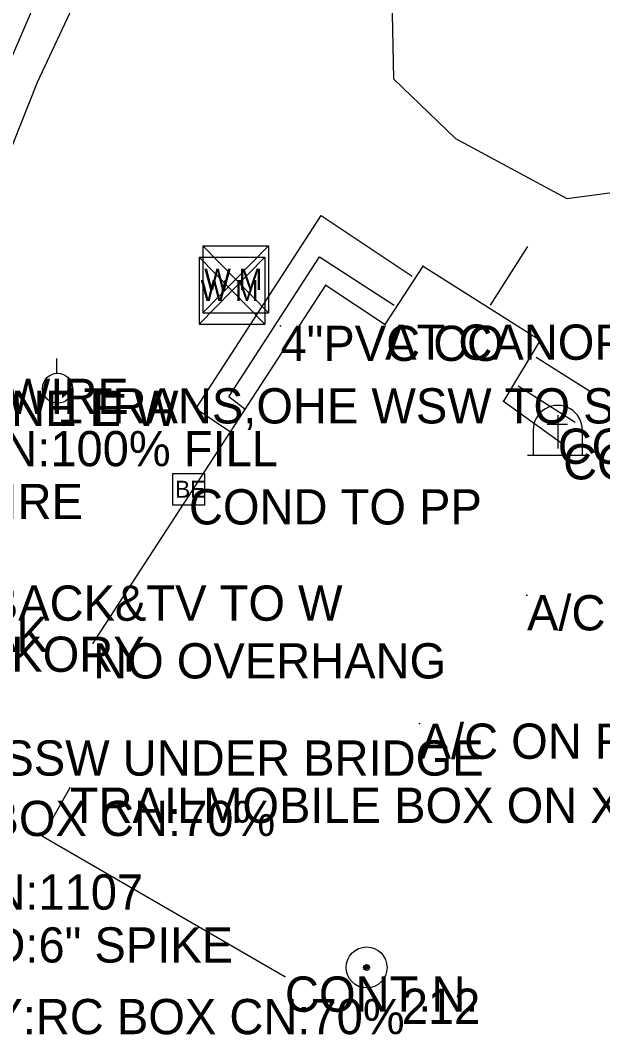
# Model space of a CAD drawing. Extents: x 997398 to 1003416, y 334596 to 337085.
# Drawn here: x 999521.1 to 999603.8, y 336058.6 to 336202.6 of the extents above; entities that cross this region are included whole.
import ezdxf

# ---------------------------------------------------------------- set-up
doc = ezdxf.new("R2010")
doc.units = 0
for name, color, linetype in [('S_BUILDING', 7, 'Continuous'), ('S_BUILDING_ANNOT', 7, 'Continuous'), ('S_CROSS_DRAIN_ANNOT', 7, 'Continuous'), ('S_DITCHLINE', 7, 'Continuous'), ('S_EDGE_PAVEMENT', 7, 'Continuous'), ('S_ELECTRIC_UTILITIES', 7, 'Continuous'), ('S_ELECTRIC_UTILITIES_ANNOT', 7, 'Continuous'), ('S_GRAVEL_ROAD', 7, 'Continuous'), ('S_GRD_PT_SYM', 7, 'Continuous'), ('S_IRON_PIN', 7, 'Continuous'), ('S_IRON_PIN_ANNOT', 7, 'Continuous'), ('S_MISC_STRUCTURES_ANNOT', 7, 'Continuous'), ('S_MISC_TOPO_POINT', 7, 'Continuous'), ('S_MSC_PT_SYM', 7, 'Continuous'), ('S_SECONDARY_CTL_ANNOT', 7, 'Continuous'), ('S_SIDE_DRAIN_ANNOT', 7, 'Continuous'), ('S_SIDEWALK', 7, 'Continuous'), ('S_STR_PT_SYM', 7, 'Continuous'), ('S_TOMBSTONE', 7, 'Continuous'), ('S_TOMBSTONE_ANNOT', 7, 'Continuous'), ('S_TREE_ANNOT', 7, 'Continuous'), ('S_UTILITY_POLE', 7, 'Continuous'), ('S_UTILITY_POLE_ANNOT', 7, 'Continuous'), ('S_WATER_UTILITIES', 7, 'Continuous')]:
    doc.layers.add(name, color=color, linetype=linetype)

msp = doc.modelspace()

# ---------------------------------------------------------------- linework, layer by layer
at = {"layer": 'S_BUILDING'}
for p, q in [((999572.9, 336159.41), (999578.28, 336167.71)), ((999578.28, 336167.71), (999594.93, 336157.21)), ((999531.42, 336114.19), (999564.46, 336164.99)), ((999564.46, 336164.99), (999572.9, 336159.41)), ((999594.93, 336157.21), (999589.73, 336148.53)), ((999589.73, 336148.53), (999598.18, 336142.43)), ((999528.11, 336093.69), (999524.25, 336086.83)), ((999524.25, 336086.83), (999558.67, 336066.9))]:
    msp.add_line(p, q, dxfattribs=at)
at = {"layer": 'S_DITCHLINE'}
msp.add_lwpolyline([(999475.43, 336077.33), (999482.6, 336095.21), (999489.77, 336113.08), (999498.51, 336133.02), (999507.25, 336152.96), (999515.39, 336173.39), (999523.54, 336193.82), (999529.15, 336205.87), (999534.77, 336217.93), (999542.66, 336236.46), (999550.55, 336255), (999557.88, 336270.85)], dxfattribs=at)
at = {"layer": 'S_EDGE_PAVEMENT'}
msp.add_lwpolyline([(999462.94, 336067.47), (999472.76, 336088.65), (999482.57, 336109.83), (999487.39, 336121.37), (999492.2, 336132.92), (999497.02, 336144.47), (999501.83, 336156.01), (999507.04, 336167.97), (999512.25, 336179.93), (999517.46, 336191.88), (999522.67, 336203.84), (999527.6, 336215.54), (999532.53, 336227.24), (999537.46, 336238.93), (999542.4, 336250.63), (999551.59, 336272.84), (999556.87, 336286.38), (999562.16, 336299.92), (999567.44, 336313.47), (999572.72, 336327.01), (999577.33, 336339.09), (999581.94, 336351.18)], dxfattribs=at)
at = {"layer": 'S_ELECTRIC_UTILITIES'}
msp.add_lwpolyline([(999542.76, 336133.79), (999542.76, 336138.29), (999547.26, 336138.29), (999547.26, 336133.79)], close=True, dxfattribs=at)
at = {"layer": 'S_GRAVEL_ROAD'}
msp.add_lwpolyline([(999576.51, 336269.96), (999583.04, 336262.6), (999586.9, 336251.61), (999584.32, 336236.92), (999579.09, 336221.38), (999573.87, 336205.84), (999574.11, 336194.28), (999582.9, 336185.79), (999598.73, 336177.31), (999616.12, 336179.59), (999629.75, 336189.17), (999638.84, 336202.7), (999643.92, 336219.19), (999644.25, 336236.84), (999637.21, 336252.76), (999624.04, 336265.72), (999603.11, 336276.06), (999594.63, 336275.8), (999585.12, 336283.33)], dxfattribs=at)
at = {"layer": 'S_GRD_PT_SYM'}
msp.add_lwpolyline([(999558.03, 336159.24), (999558.03, 336159.29), (999558.03, 336159.24), (999557.98, 336159.24), (999558.03, 336159.24), (999558.03, 336159.19), (999558.03, 336159.24), (999558.08, 336159.24)], dxfattribs=at)
at = {"layer": 'S_IRON_PIN'}
for radius in [2.91, 0.411, 0.262, 0.212, 0.145, 0.0822, 0.0581]:
    msp.add_circle((999570.26, 336068.18), radius, dxfattribs=at)
at = {"layer": 'S_MSC_PT_SYM'}
for points in [[(999593.05, 336121.01), (999593.05, 336121.06), (999593.05, 336121.01), (999593, 336121.01), (999593.05, 336121.01), (999593.05, 336120.96), (999593.05, 336121.01), (999593.1, 336121.01)], [(999577.8, 336102.79), (999577.8, 336102.84), (999577.8, 336102.79), (999577.75, 336102.79), (999577.8, 336102.79), (999577.8, 336102.74), (999577.8, 336102.79), (999577.85, 336102.79)]]:
    msp.add_lwpolyline(points, dxfattribs=at)
at = {"layer": 'S_SIDEWALK'}
for points in [[(999550.8, 336144.21), (999546.03, 336147.44), (999554.93, 336161.15), (999563.83, 336174.87), (999576.76, 336166.29)], [(999593.12, 336170.48), (999587.8, 336162.18)], [(999552.95, 336147.41), (999550.68, 336149.15), (999563.58, 336169), (999574.17, 336162.15)], [(999594.34, 336154.8), (999602.47, 336149.68)], [(999591.79, 336150.71), (999599.87, 336145.55)]]:
    msp.add_lwpolyline(points, dxfattribs=at)
at = {"layer": 'S_STR_PT_SYM'}
for points in [[(999578.28, 336167.71), (999578.28, 336167.76), (999578.28, 336167.71), (999578.23, 336167.71), (999578.28, 336167.71), (999578.28, 336167.66), (999578.28, 336167.71), (999578.33, 336167.71)], [(999564.46, 336164.99), (999564.46, 336165.04), (999564.46, 336164.99), (999564.41, 336164.99), (999564.46, 336164.99), (999564.46, 336164.94), (999564.46, 336164.99), (999564.51, 336164.99)], [(999572.9, 336159.41), (999572.9, 336159.46), (999572.9, 336159.41), (999572.85, 336159.41), (999572.9, 336159.41), (999572.9, 336159.36), (999572.9, 336159.41), (999572.95, 336159.41)], [(999594.93, 336157.21), (999594.93, 336157.26), (999594.93, 336157.21), (999594.88, 336157.21), (999594.93, 336157.21), (999594.93, 336157.16), (999594.93, 336157.21), (999594.98, 336157.21)], [(999589.73, 336148.53), (999589.73, 336148.58), (999589.73, 336148.53), (999589.68, 336148.53), (999589.73, 336148.53), (999589.73, 336148.48), (999589.73, 336148.53), (999589.78, 336148.53)], [(999598.18, 336142.43), (999598.18, 336142.48), (999598.18, 336142.43), (999598.13, 336142.43), (999598.18, 336142.43), (999598.18, 336142.38), (999598.18, 336142.43), (999598.23, 336142.43)], [(999531.42, 336114.19), (999531.42, 336114.24), (999531.42, 336114.19), (999531.37, 336114.19), (999531.42, 336114.19), (999531.42, 336114.14), (999531.42, 336114.19), (999531.47, 336114.19)], [(999528.11, 336093.69), (999528.11, 336093.74), (999528.11, 336093.69), (999528.06, 336093.69), (999528.11, 336093.69), (999528.11, 336093.64), (999528.11, 336093.69), (999528.16, 336093.69)], [(999524.25, 336086.83), (999524.25, 336086.88), (999524.25, 336086.83), (999524.2, 336086.83), (999524.25, 336086.83), (999524.25, 336086.78), (999524.25, 336086.83), (999524.3, 336086.83)], [(999558.67, 336066.9), (999558.67, 336066.95), (999558.67, 336066.9), (999558.62, 336066.9), (999558.67, 336066.9), (999558.67, 336066.85), (999558.67, 336066.9), (999558.72, 336066.9)]]:
    msp.add_lwpolyline(points, dxfattribs=at)
at = {"layer": 'S_TOMBSTONE'}
for p, q in [((999597.42, 336146.55), (999597.42, 336141.82)), ((999595.91, 336145.27), (999598.78, 336145.27)), ((999593.94, 336144.42), (999593.94, 336140.89)), ((999600.91, 336144.42), (999600.91, 336140.97)), ((999593.12, 336140.89), (999601.69, 336140.89))]:
    msp.add_line(p, q, dxfattribs=at)
msp.add_arc((999597.42, 336144.45), 3.49, 359.3489, 180.6228, dxfattribs=at)
at = {"layer": 'S_UTILITY_POLE'}
msp.add_line((999526.25, 336152.51), (999526.25, 336154.61), dxfattribs=at)
msp.add_circle((999526.37, 336150.37), 2.13, dxfattribs=at)
at = {"layer": 'S_WATER_UTILITIES'}
for p, q in [((999547, 336170.56), (999556.33, 336170.56)), ((999547, 336170.56), (999547, 336161.07)), ((999547, 336170.56), (999556.33, 336161.07)), ((999556.33, 336170.56), (999547, 336161.07)), ((999556.33, 336170.56), (999556.33, 336161.07)), ((999546.48, 336168.96), (999555.82, 336168.96)), ((999546.48, 336168.96), (999546.48, 336159.47)), ((999546.48, 336168.96), (999555.82, 336159.47)), ((999555.82, 336168.96), (999546.48, 336159.47)), ((999555.82, 336168.96), (999555.82, 336159.47)), ((999547, 336161.07), (999556.33, 336161.07)), ((999546.48, 336159.47), (999555.82, 336159.47))]:
    msp.add_line(p, q, dxfattribs=at)

# ---------------------------------------------------------------- texts
at = {"layer": 'S_BUILDING_ANNOT'}
for s, p in [('AT CANOPY', (999572.9, 336154.41)), ('CONT.S.', (999598.18, 336137.43)), ('NO OVERHANG', (999531.42, 336109.19)), ('TRAILMOBILE BOX ON X-TI.. ES,NO', (999528.11, 336088.69)), ('CONT.N.', (999558.67, 336061.9))]:
    msp.add_text(s, height=5, dxfattribs=at).set_placement(p)
at = {"layer": 'S_CROSS_DRAIN_ANNOT'}
for p in [(999448.43, 336086.83), (999466.81, 336058.71)]:
    msp.add_text('WD:6.0 HT:3.0 TY:RC BOX CN:70% ', height=5, dxfattribs=at).set_placement(p)
at = {"layer": 'S_ELECTRIC_UTILITIES'}
msp.add_text('BE', height=2.4, rotation=360, dxfattribs=at).set_placement((999543.07, 336134.84))
at = {"layer": 'S_ELECTRIC_UTILITIES_ANNOT'}
for s, p in [('LOWEST WIRE', (999488.93, 336146.72)), ('LOWEST WIRE', (999482.44, 336131.8)), ('COND TO PP', (999545.03, 336131.04))]:
    msp.add_text(s, height=5, dxfattribs=at).set_placement(p)
at = {"layer": 'S_IRON_PIN_ANNOT'}
msp.add_text('212', height=5, dxfattribs=at).set_placement((999575.26, 336060.18))
at = {"layer": 'S_MISC_STRUCTURES_ANNOT'}
for p in [(999593.05, 336116.01), (999577.8, 336097.79)]:
    msp.add_text('A/C ON RESIN PAD', height=5, dxfattribs=at).set_placement(p)
at = {"layer": 'S_MISC_TOPO_POINT'}
msp.add_text('4"PVC CO', height=5, dxfattribs=at).set_placement((999558.03, 336154.24))
at = {"layer": 'S_SECONDARY_CTL_ANNOT'}
for s, p in [('PN:1107', (999512.51, 336076.38)), ('PD:6" SPIKE', (999512.51, 336068.88))]:
    msp.add_text(s, height=5, dxfattribs=at).set_placement(p)
at = {"layer": 'S_SIDE_DRAIN_ANNOT'}
msp.add_text('DI:24 TY:CMP CN:100% FILL', height=5, dxfattribs=at).set_placement((999468.87, 336139.3))
at = {"layer": 'S_TOMBSTONE_ANNOT'}
msp.add_text("CONC MASON'S MON", height=5, dxfattribs=at).set_placement((999597.42, 336139.64))
at = {"layer": 'S_TREE_ANNOT'}
for s, p in [('12OAK', (999503.45, 336112.94)), ('22HICKORY', (999500.84, 336110.13))]:
    msp.add_text(s, height=5, dxfattribs=at).set_placement(p)
at = {"layer": 'S_UTILITY_POLE_ANNOT'}
for s, p in [('W/LIGHT,OHE NNE NE E W', (999457.73, 336145.01)), ('1TRANS,OHE WSW TO S PP', (999526.37, 336145.37)), ('TIEBACK&TV TO W', (999505.92, 336117.38)), ('OHT NNE,SSW UNDER BRIDGE', (999486.59, 336095.4))]:
    msp.add_text(s, height=5, dxfattribs=at).set_placement(p)
at = {"layer": 'S_WATER_UTILITIES'}
for p in [(999547.2, 336164.33), (999546.69, 336162.73)]:
    msp.add_text('W M', height=3, rotation=360, dxfattribs=at).set_placement(p)

doc.saveas('drawing.dxf')
